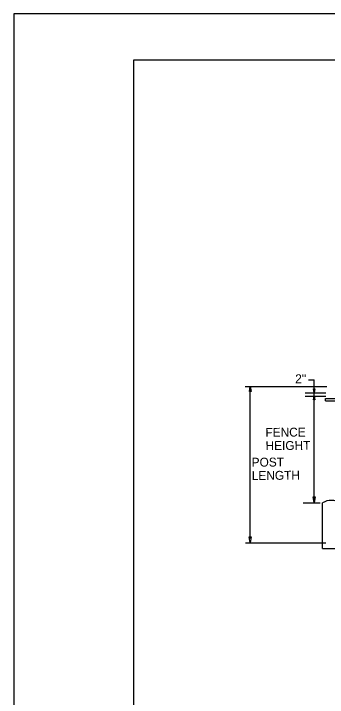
# Model space of a CAD drawing. Extents: x 0 to 2.85, y -0.1 to 1.83.
# Drawn here: x 0 to 0.354, y 1.063 to 1.833 of the extents above; entities that cross this region are included whole.
import ezdxf

# ---------------------------------------------------------------- set-up
doc = ezdxf.new("R2010")
doc.units = 0
for name, color, linetype in [('BDR_Inner_Perimeter', 7, 'Continuous'), ('BDR_Outer_Perimeter', 7, 'Continuous'), ('CT_Dimensions', 7, 'Continuous'), ('sb_Existing Concrete', 7, 'Continuous'), ('sb_Existing Structural Steel', 7, 'Continuous')]:
    doc.layers.add(name, color=color, linetype=linetype)

msp = doc.modelspace()

# ---------------------------------------------------------------- linework, layer by layer
at = {"layer": 'BDR_Inner_Perimeter'}
msp.add_lwpolyline([(0.13539, 1.78125), (2.78123, 1.78125), (2.78123, 0.05208), (0.13539, 0.05208)], close=True, dxfattribs=at)
at = {"layer": 'BDR_Outer_Perimeter'}
msp.add_lwpolyline([(0, 0), (2.83333, 0), (2.83333, 1.83333), (0, 1.83333)], close=True, dxfattribs=at)
at = {"layer": 'CT_Dimensions'}
for p, q in [((0.33871, 1.42048), (0.33227, 1.42048)), ((0.33868, 1.40215), (0.33867, 1.42052)), ((0.26103, 1.41318), (0.35316, 1.41318)), ((0.26669, 1.24193), (0.26669, 1.41245)), ((0.32839, 1.40244), (0.35193, 1.40244)), ((0.32843, 1.40603), (0.35193, 1.40603)), ((0.33862, 1.28219), (0.33862, 1.39981)), ((0.3264, 1.28219), (0.34533, 1.28219)), ((0.26131, 1.23709), (0.352, 1.23709))]:
    msp.add_line(p, q, dxfattribs=at)
for points in [[(0.26576, 1.40769), (0.26668, 1.41318), (0.26759, 1.40769)], [(0.33941, 1.41045), (0.33867, 1.406), (0.33793, 1.41045)], [(0.3379, 1.39799), (0.33864, 1.40244), (0.33938, 1.39799)], [(0.33977, 1.28895), (0.33862, 1.28209), (0.33748, 1.28895)], [(0.26776, 1.24379), (0.26662, 1.23693), (0.26547, 1.24379)]]:
    msp.add_lwpolyline(points, close=True, dxfattribs=at)
at = {"layer": 'sb_Existing Concrete'}
for q in [(0.34822, 1.28212), (0.36844, 1.2305)]:
    msp.add_line((0.34823, 1.2305), q, dxfattribs=at)
msp.add_arc((0.35827, 1.2645), 0.02029, 59.95295, 119.68756, dxfattribs=at)
at = {"layer": 'sb_Existing Structural Steel'}
for p, q in [((0.35152, 1.39975), (0.3701, 1.39975)), ((0.35152, 1.39698), (0.35152, 1.39975)), ((0.35152, 1.39698), (0.3701, 1.39698))]:
    msp.add_line(p, q, dxfattribs=at)

# ---------------------------------------------------------------- texts
at = {"layer": 'CT_Dimensions'}
msp.add_text("2'' ", height=0.01, dxfattribs=at).set_placement((0.31731, 1.4169))
for s, p in [('FENCE ', (0.28381, 1.35647)), ('HEIGHT', (0.28392, 1.34147)), ('POST', (0.2683, 1.32281)), ('LENGTH', (0.26842, 1.30781))]:
    msp.add_text(s, height=0.01, rotation=0.42564, dxfattribs=at).set_placement(p)

doc.saveas('drawing.dxf')
